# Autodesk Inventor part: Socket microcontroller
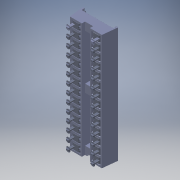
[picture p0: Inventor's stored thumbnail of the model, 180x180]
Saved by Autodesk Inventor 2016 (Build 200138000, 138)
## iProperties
Created: 2018-03
Part Number: Socket microcontroller
Material: Générique
Document SubType Name: Modeling
Designer: Bruno
Density: 1 g/cm^3
Appearance: Par défaut
Author: Bruno
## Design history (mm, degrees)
feature "Composite1"
body "Srf1"
